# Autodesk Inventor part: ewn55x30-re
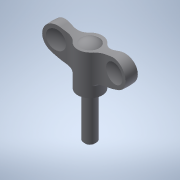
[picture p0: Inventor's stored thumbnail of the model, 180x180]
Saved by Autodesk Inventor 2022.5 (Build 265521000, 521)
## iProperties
Created: 2016-12
Part Number: ewn55x30-re
Material: 一般
Document SubType Name: Modeling
Designer: imaocorp
Density: 1 g/cm^3
Appearance: 既定
Author: imaocorp
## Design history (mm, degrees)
node "ewn55x30-re.x_t1"
node "ewn55x30-re"
node "Base1"
